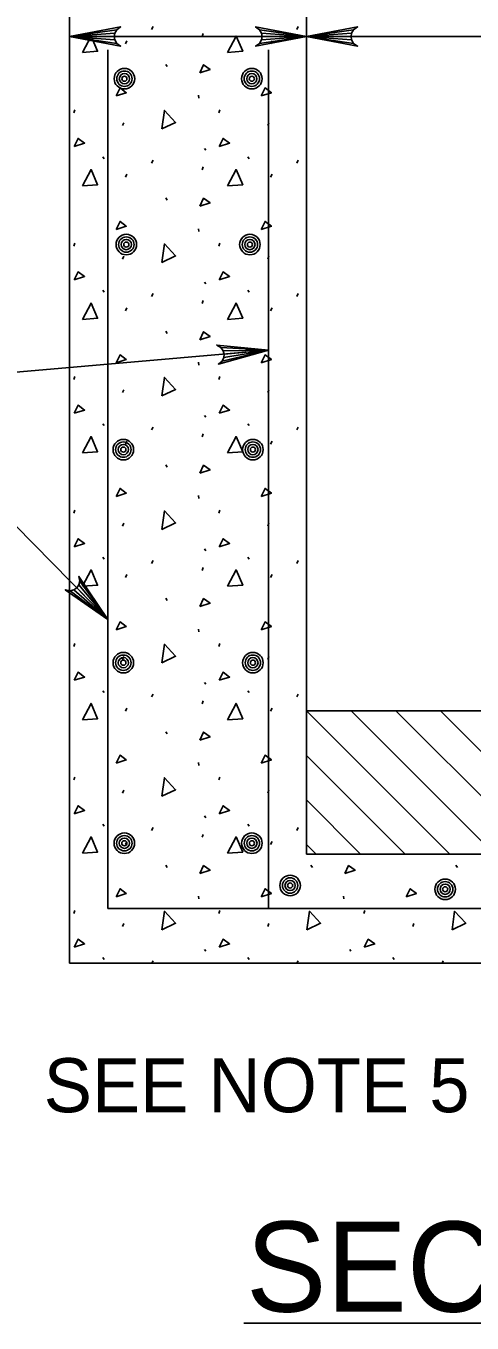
# Model space of a CAD drawing. Extents: x 6.91 to 13.84, y 0.35 to 9.99.
# Drawn here: x 8.037 to 8.532, y 2.3 to 3.739 of the extents above; entities that cross this region are included whole.
import ezdxf

# ---------------------------------------------------------------- set-up
doc = ezdxf.new("R2010")
doc.units = 0
for name, color, linetype in [('Default', 7, 'Continuous'), ('DETL-DIMS', 7, 'Continuous'), ('DETL-LINE', 7, 'Continuous'), ('DETL-NOTE', 7, 'Continuous'), ('DETL-TITL', 7, 'Continuous')]:
    doc.layers.add(name, color=color, linetype=linetype)

msp = doc.modelspace()

# ---------------------------------------------------------------- linework, layer by layer
at = {"layer": 'Default'}
for p, q in [((8.1767, 3.7353), (8.1783, 3.7386)), ((8.2327, 3.7277), (8.2339, 3.7309)), ((8.3378, 3.7353), (8.3394, 3.7386)), ((8.1477, 3.7196), (8.1493, 3.7229)), ((8.3088, 3.7196), (8.3104, 3.7229)), ((8.1924, 3.6967), (8.194, 3.6943)), ((8.2287, 3.6625), (8.2291, 3.6593)), ((8.0902, 3.6431), (8.0914, 3.6464)), ((8.2512, 3.6431), (8.2524, 3.6464)), ((8.1445, 3.6287), (8.1457, 3.6319)), ((8.3055, 3.6287), (8.3068, 3.6319)), ((8.2355, 3.6033), (8.2367, 3.6013)), ((8.1224, 3.594), (8.124, 3.592)), ((8.1767, 3.5872), (8.1783, 3.5904)), ((8.2834, 3.594), (8.285, 3.592)), ((8.3378, 3.5872), (8.3394, 3.5904)), ((8.1477, 3.5715), (8.1493, 3.5747)), ((8.2327, 3.5795), (8.2339, 3.5828)), ((8.3088, 3.5715), (8.3104, 3.5747)), ((8.1924, 3.5485), (8.194, 3.5461)), ((8.2287, 3.5143), (8.2291, 3.5111)), ((8.0902, 3.495), (8.0914, 3.4982)), ((8.2512, 3.495), (8.2524, 3.4982)), ((8.1445, 3.4805), (8.1457, 3.4837)), ((8.3055, 3.4805), (8.3068, 3.4837)), ((8.1224, 3.4459), (8.124, 3.4439)), ((8.1767, 3.439), (8.1783, 3.4423)), ((8.2355, 3.4551), (8.2367, 3.4531)), ((8.2834, 3.4459), (8.285, 3.4439)), ((8.3378, 3.439), (8.3394, 3.4423)), ((8.2327, 3.4314), (8.2339, 3.4346)), ((8.1477, 3.4233), (8.1493, 3.4266)), ((8.3088, 3.4233), (8.3104, 3.4266)), ((8.1924, 3.4004), (8.194, 3.398)), ((8.2287, 3.3662), (8.2291, 3.363)), ((8.0902, 3.3469), (8.0914, 3.3501)), ((8.2512, 3.3469), (8.2524, 3.3501)), ((8.1445, 3.3324), (8.1457, 3.3356)), ((8.3055, 3.3324), (8.3068, 3.3356)), ((8.1224, 3.2977), (8.124, 3.2957)), ((8.2355, 3.307), (8.2367, 3.305)), ((8.2834, 3.2977), (8.285, 3.2957)), ((8.1767, 3.2909), (8.1783, 3.2941)), ((8.2327, 3.2832), (8.2339, 3.2865)), ((8.3378, 3.2909), (8.3394, 3.2941)), ((8.1477, 3.2752), (8.1493, 3.2784)), ((8.3088, 3.2752), (8.3104, 3.2784)), ((8.1924, 3.2522), (8.194, 3.2498)), ((8.2287, 3.218), (8.2291, 3.2148)), ((8.0902, 3.1987), (8.0914, 3.2019)), ((8.2512, 3.1987), (8.2524, 3.2019)), ((8.1445, 3.1842), (8.1457, 3.1874)), ((8.3055, 3.1842), (8.3068, 3.1874)), ((8.2355, 3.1589), (8.2367, 3.1568)), ((8.1224, 3.1496), (8.124, 3.1476)), ((8.1767, 3.1427), (8.1783, 3.146)), ((8.2834, 3.1496), (8.285, 3.1476)), ((8.3378, 3.1427), (8.3394, 3.146)), ((8.1477, 3.127), (8.1493, 3.1303)), ((8.2327, 3.1351), (8.2339, 3.1383)), ((8.3088, 3.127), (8.3104, 3.1303)), ((8.1924, 3.1041), (8.194, 3.1017)), ((8.2287, 3.0699), (8.2291, 3.0667)), ((8.0902, 3.0506), (8.0914, 3.0538)), ((8.2512, 3.0506), (8.2524, 3.0538)), ((8.1445, 3.0361), (8.1457, 3.0393)), ((8.3055, 3.0361), (8.3068, 3.0393)), ((8.2355, 3.0107), (8.2367, 3.0087)), ((8.1224, 3.0014), (8.124, 2.9994)), ((8.1767, 2.9946), (8.1783, 2.9978)), ((8.2834, 3.0014), (8.285, 2.9994)), ((8.3378, 2.9946), (8.3394, 2.9978)), ((8.1477, 2.9789), (8.1493, 2.9821)), ((8.2327, 2.987), (8.2339, 2.9902)), ((8.3088, 2.9789), (8.3104, 2.9821)), ((8.3487, 2.9792), (8.5077, 2.8202)), ((8.3982, 2.9792), (8.5572, 2.8202)), ((8.4477, 2.9792), (8.6067, 2.8202)), ((8.4972, 2.9792), (8.6562, 2.8202)), ((8.1924, 2.956), (8.194, 2.9535)), ((8.3487, 2.9297), (8.4582, 2.8202)), ((8.2287, 2.9217), (8.2291, 2.9185)), ((8.0902, 2.9024), (8.0914, 2.9056)), ((8.2512, 2.9024), (8.2524, 2.9056)), ((8.1445, 2.8879), (8.1457, 2.8911)), ((8.3055, 2.8879), (8.3068, 2.8911)), ((8.3487, 2.8802), (8.4087, 2.8202)), ((8.1224, 2.8533), (8.124, 2.8513)), ((8.2355, 2.8626), (8.2367, 2.8605)), ((8.2834, 2.8533), (8.285, 2.8513)), ((8.1767, 2.8465), (8.1783, 2.8497)), ((8.2327, 2.8388), (8.2339, 2.842)), ((8.3378, 2.8465), (8.3394, 2.8497)), ((8.1477, 2.8308), (8.1493, 2.834)), ((8.3088, 2.8308), (8.3104, 2.834)), ((8.3487, 2.8307), (8.3592, 2.8202)), ((8.1924, 2.8078), (8.194, 2.8054)), ((8.3535, 2.8078), (8.3551, 2.8054)), ((8.5145, 2.8078), (8.5161, 2.8054)), ((8.2287, 2.7736), (8.2291, 2.7704)), ((8.3897, 2.7736), (8.3901, 2.7704)), ((8.0902, 2.7543), (8.0914, 2.7575)), ((8.2512, 2.7543), (8.2524, 2.7575)), ((8.4122, 2.7543), (8.4134, 2.7575)), ((8.1445, 2.7398), (8.1457, 2.743)), ((8.3055, 2.7398), (8.3068, 2.743)), ((8.4666, 2.7398), (8.4678, 2.743)), ((8.2355, 2.7144), (8.2367, 2.7124)), ((8.3965, 2.7144), (8.3977, 2.7124)), ((8.1224, 2.7052), (8.124, 2.7031)), ((8.177, 2.6989), (8.1783, 2.7015)), ((8.2834, 2.7052), (8.285, 2.7031)), ((8.338, 2.6989), (8.3394, 2.7015)), ((8.4444, 2.7052), (8.446, 2.7031)), ((8.4991, 2.6989), (8.5004, 2.7015))]:
    msp.add_line(p, q, dxfattribs=at)
for points in [[(8.0998, 3.71), (8.1095, 3.7281), (8.1167, 3.7112), (8.0998, 3.71)], [(8.2609, 3.71), (8.2705, 3.7281), (8.2778, 3.7112), (8.2609, 3.71)], [(8.2303, 3.6874), (8.2343, 3.6963), (8.2415, 3.6911), (8.2303, 3.6874)], [(8.1373, 3.6617), (8.1417, 3.6705), (8.1485, 3.6653), (8.1373, 3.6617)], [(8.2983, 3.6617), (8.3027, 3.6705), (8.3096, 3.6653), (8.2983, 3.6617)], [(8.188, 3.625), (8.1908, 3.6456), (8.2033, 3.6323), (8.188, 3.625)], [(8.0906, 3.6057), (8.095, 3.6146), (8.1022, 3.6093), (8.0906, 3.6057)], [(8.2516, 3.6057), (8.256, 3.6146), (8.2633, 3.6093), (8.2516, 3.6057)], [(8.0998, 3.5618), (8.1095, 3.5799), (8.1167, 3.563), (8.0998, 3.5618)], [(8.2609, 3.5618), (8.2705, 3.5799), (8.2778, 3.563), (8.2609, 3.5618)], [(8.2303, 3.5393), (8.2343, 3.5481), (8.2415, 3.5429), (8.2303, 3.5393)], [(8.1373, 3.5135), (8.1417, 3.5224), (8.1485, 3.5171), (8.1373, 3.5135)], [(8.2983, 3.5135), (8.3027, 3.5224), (8.3096, 3.5171), (8.2983, 3.5135)], [(8.188, 3.4769), (8.1908, 3.4974), (8.2033, 3.4841), (8.188, 3.4769)], [(8.0906, 3.4576), (8.095, 3.4664), (8.1022, 3.4612), (8.0906, 3.4576)], [(8.2516, 3.4576), (8.256, 3.4664), (8.2633, 3.4612), (8.2516, 3.4576)], [(8.0998, 3.4137), (8.1095, 3.4318), (8.1167, 3.4149), (8.0998, 3.4137)], [(8.2609, 3.4137), (8.2705, 3.4318), (8.2778, 3.4149), (8.2609, 3.4137)], [(8.2303, 3.3911), (8.2343, 3.4), (8.2415, 3.3948), (8.2303, 3.3911)], [(8.1373, 3.3654), (8.1417, 3.3742), (8.1485, 3.369), (8.1373, 3.3654)], [(8.2983, 3.3654), (8.3027, 3.3742), (8.3096, 3.369), (8.2983, 3.3654)], [(8.188, 3.3287), (8.1908, 3.3493), (8.2033, 3.336), (8.188, 3.3287)], [(8.0906, 3.3094), (8.095, 3.3183), (8.1022, 3.313), (8.0906, 3.3094)], [(8.2516, 3.3094), (8.256, 3.3183), (8.2633, 3.313), (8.2516, 3.3094)], [(8.0998, 3.2655), (8.1095, 3.2836), (8.1167, 3.2667), (8.0998, 3.2655)], [(8.2609, 3.2655), (8.2705, 3.2836), (8.2778, 3.2667), (8.2609, 3.2655)], [(8.2303, 3.243), (8.2343, 3.2518), (8.2415, 3.2466), (8.2303, 3.243)], [(8.1373, 3.2172), (8.1417, 3.2261), (8.1485, 3.2208), (8.1373, 3.2172)], [(8.2983, 3.2172), (8.3027, 3.2261), (8.3096, 3.2208), (8.2983, 3.2172)], [(8.188, 3.1806), (8.1908, 3.2011), (8.2033, 3.1878), (8.188, 3.1806)], [(8.0906, 3.1613), (8.095, 3.1701), (8.1022, 3.1649), (8.0906, 3.1613)], [(8.2516, 3.1613), (8.256, 3.1701), (8.2633, 3.1649), (8.2516, 3.1613)], [(8.0998, 3.1174), (8.1095, 3.1355), (8.1167, 3.1186), (8.0998, 3.1174)], [(8.2609, 3.1174), (8.2705, 3.1355), (8.2778, 3.1186), (8.2609, 3.1174)], [(8.2303, 3.0948), (8.2343, 3.1037), (8.2415, 3.0985), (8.2303, 3.0948)], [(8.1373, 3.0691), (8.1417, 3.0779), (8.1485, 3.0727), (8.1373, 3.0691)], [(8.2983, 3.0691), (8.3027, 3.0779), (8.3096, 3.0727), (8.2983, 3.0691)], [(8.188, 3.0324), (8.1908, 3.053), (8.2033, 3.0397), (8.188, 3.0324)], [(8.0906, 3.0131), (8.095, 3.022), (8.1022, 3.0167), (8.0906, 3.0131)], [(8.2516, 3.0131), (8.256, 3.022), (8.2633, 3.0167), (8.2516, 3.0131)], [(8.0998, 2.9692), (8.1095, 2.9874), (8.1167, 2.9704), (8.0998, 2.9692)], [(8.2609, 2.9692), (8.2705, 2.9874), (8.2778, 2.9704), (8.2609, 2.9692)], [(8.2303, 2.9467), (8.2343, 2.9556), (8.2415, 2.9503), (8.2303, 2.9467)], [(8.1373, 2.9209), (8.1417, 2.9298), (8.1485, 2.9246), (8.1373, 2.9209)], [(8.2983, 2.9209), (8.3027, 2.9298), (8.3096, 2.9246), (8.2983, 2.9209)], [(8.188, 2.8843), (8.1908, 2.9048), (8.2033, 2.8915), (8.188, 2.8843)], [(8.0906, 2.865), (8.095, 2.8738), (8.1022, 2.8686), (8.0906, 2.865)], [(8.2516, 2.865), (8.256, 2.8738), (8.2633, 2.8686), (8.2516, 2.865)], [(8.0998, 2.8211), (8.1095, 2.8392), (8.1167, 2.8223), (8.0998, 2.8211)], [(8.2609, 2.8211), (8.2705, 2.8392), (8.2778, 2.8223), (8.2609, 2.8211)], [(8.2303, 2.7985), (8.2343, 2.8074), (8.2415, 2.8022), (8.2303, 2.7985)], [(8.3913, 2.7985), (8.3953, 2.8074), (8.4026, 2.8022), (8.3913, 2.7985)], [(8.1373, 2.7728), (8.1417, 2.7816), (8.1485, 2.7764), (8.1373, 2.7728)], [(8.2983, 2.7728), (8.3027, 2.7816), (8.3096, 2.7764), (8.2983, 2.7728)], [(8.4593, 2.7728), (8.4638, 2.7816), (8.4706, 2.7764), (8.4593, 2.7728)], [(8.188, 2.7361), (8.1908, 2.7567), (8.2033, 2.7434), (8.188, 2.7361)], [(8.349, 2.7361), (8.3518, 2.7567), (8.3643, 2.7434), (8.349, 2.7361)], [(8.5101, 2.7361), (8.5129, 2.7567), (8.5254, 2.7434), (8.5101, 2.7361)], [(8.0906, 2.7168), (8.095, 2.7257), (8.1022, 2.7204), (8.0906, 2.7168)], [(8.2516, 2.7168), (8.256, 2.7257), (8.2633, 2.7204), (8.2516, 2.7168)], [(8.4126, 2.7168), (8.4171, 2.7257), (8.4243, 2.7204), (8.4126, 2.7168)]]:
    msp.add_lwpolyline(points, dxfattribs=at)
at = {"layer": 'DETL-DIMS'}
for p, q in [((8.0857, 3.7276), (8.3487, 3.7276)), ((8.3487, 3.7276), (9.2184, 3.7276)), ((7.8713, 3.3415), (8.3063, 3.3795)), ((7.8713, 3.3415), (8.1281, 3.0806))]:
    msp.add_line(p, q, dxfattribs=at)
for points in [[(8.0857, 3.7276), (8.1423, 3.7382), (8.1379, 3.7351), (8.1357, 3.7314), (8.135, 3.7276), (8.1357, 3.7238), (8.1379, 3.72), (8.1423, 3.717), (8.0857, 3.7276), (8.1379, 3.72), (8.1357, 3.7238), (8.0857, 3.7276), (8.135, 3.7276), (8.1357, 3.7314), (8.0857, 3.7276), (8.1379, 3.7351)], [(8.3487, 3.7276), (8.2921, 3.717), (8.2965, 3.72), (8.2987, 3.7238), (8.2994, 3.7276), (8.2987, 3.7314), (8.2965, 3.7351), (8.2921, 3.7382), (8.3487, 3.7276), (8.2965, 3.7351), (8.2987, 3.7314), (8.3487, 3.7276), (8.2994, 3.7276), (8.2987, 3.7238), (8.3487, 3.7276), (8.2965, 3.72)], [(8.3487, 3.7276), (8.4052, 3.717), (8.4009, 3.72), (8.3986, 3.7238), (8.398, 3.7276), (8.3986, 3.7314), (8.4009, 3.7351), (8.4052, 3.7382), (8.3487, 3.7276), (8.4009, 3.7351), (8.3986, 3.7314), (8.3487, 3.7276), (8.398, 3.7276), (8.3986, 3.7238), (8.3487, 3.7276), (8.4009, 3.72)], [(8.3063, 3.3795), (8.2509, 3.364), (8.255, 3.3674), (8.2569, 3.3714), (8.2572, 3.3752), (8.2562, 3.3789), (8.2536, 3.3825), (8.249, 3.3851), (8.3063, 3.3795), (8.2536, 3.3825), (8.2562, 3.3789), (8.3063, 3.3795), (8.2572, 3.3752), (8.2569, 3.3714), (8.3063, 3.3795), (8.255, 3.3674)], [(8.1281, 3.0806), (8.0809, 3.1135), (8.0861, 3.1125), (8.0904, 3.1135), (8.0935, 3.1157), (8.0958, 3.1189), (8.0969, 3.1231), (8.096, 3.1284), (8.1281, 3.0806), (8.0969, 3.1231), (8.0958, 3.1189), (8.1281, 3.0806), (8.0935, 3.1157), (8.0904, 3.1135), (8.1281, 3.0806), (8.0861, 3.1125)]]:
    msp.add_lwpolyline(points, dxfattribs=at)
at = {"layer": 'DETL-LINE'}
for p, q in [((8.0857, 2.6989), (8.0857, 4.1753)), ((8.3487, 2.8202), (8.3487, 4.1519)), ((8.1281, 2.7596), (8.1281, 3.7127)), ((8.3063, 2.7596), (8.3063, 3.7127)), ((8.3487, 2.9792), (9.2184, 2.9792)), ((8.3487, 2.8202), (9.2184, 2.8202)), ((8.3063, 2.7596), (8.1281, 2.7596)), ((8.3063, 2.7596), (9.256, 2.7596)), ((8.0857, 2.6989), (9.4813, 2.6989))]:
    msp.add_line(p, q, dxfattribs=at)
for centre, radius in [((8.1465, 3.6808), 0.0114), ((8.1465, 3.6808), 0.00853), ((8.1465, 3.6808), 0.00569), ((8.2879, 3.6808), 0.0114), ((8.2879, 3.6808), 0.00853), ((8.2879, 3.6808), 0.00569), ((8.1465, 3.6808), 0.00284), ((8.2879, 3.6808), 0.00284), ((8.1486, 3.4967), 0.0114), ((8.1486, 3.4967), 0.00853), ((8.1486, 3.4967), 0.00569), ((8.1486, 3.4967), 0.00284), ((8.2858, 3.4967), 0.0114), ((8.2858, 3.4967), 0.00853), ((8.2858, 3.4967), 0.00569), ((8.2858, 3.4967), 0.00284), ((8.1453, 3.2691), 0.0114), ((8.1453, 3.2691), 0.00853), ((8.1453, 3.2691), 0.00569), ((8.1453, 3.2691), 0.00284), ((8.2891, 3.2691), 0.0114), ((8.2891, 3.2691), 0.00853), ((8.2891, 3.2691), 0.00569), ((8.2891, 3.2691), 0.00284), ((8.1453, 3.0326), 0.0114), ((8.1453, 3.0326), 0.00853), ((8.1453, 3.0326), 0.00569), ((8.2891, 3.0326), 0.0114), ((8.2891, 3.0326), 0.00853), ((8.2891, 3.0326), 0.00569), ((8.1453, 3.0326), 0.00284), ((8.2891, 3.0326), 0.00284), ((8.1464, 2.8322), 0.0114), ((8.1464, 2.8322), 0.00853), ((8.1464, 2.8322), 0.00569), ((8.288, 2.8322), 0.0114), ((8.288, 2.8322), 0.00853), ((8.288, 2.8322), 0.00569), ((8.1464, 2.8322), 0.00284), ((8.288, 2.8322), 0.00284), ((8.3304, 2.7853), 0.0114), ((8.3304, 2.7853), 0.00853), ((8.3304, 2.7853), 0.00569), ((8.3304, 2.7853), 0.00284), ((8.5025, 2.7811), 0.0114), ((8.5025, 2.7811), 0.00853), ((8.5025, 2.7811), 0.00569), ((8.5025, 2.7811), 0.00284)]:
    msp.add_circle(centre, radius, dxfattribs=at)
at = {"layer": 'DETL-TITL'}
msp.add_line((8.2789, 2.2996), (9.2881, 2.2996), dxfattribs=at)

# ---------------------------------------------------------------- texts
at = {"layer": 'DETL-NOTE'}
msp.add_text('SEE NOTE 5', height=0.06, dxfattribs=at).set_placement((8.0569, 2.5336))
at = {"layer": 'DETL-TITL'}
msp.add_text('SECTION B-B', height=0.100117, dxfattribs=at).set_placement((8.2814, 2.3122))

doc.saveas('drawing.dxf')
